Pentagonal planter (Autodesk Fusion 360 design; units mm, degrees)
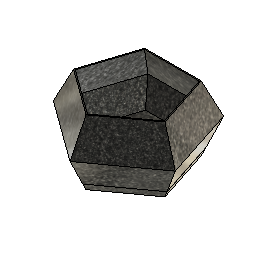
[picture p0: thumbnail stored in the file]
sketch "Sketch1" plane through (0, 0, 0) normal (0, 0, 1) x axis (1, 0, 0)
  line L1 (-70.5342, -22.918) -> (-43.5926, 60)
  line L2 (0, -74.1641) -> (-70.5342, -22.918)
  line L3 (70.5342, -22.918) -> (0, -74.1641)
  line L4 (43.5926, 60) -> (70.5342, -22.918)
  line L5 (-43.5926, 60) -> (43.5926, 60)
  point P1 (0, 0)
  point P7 (0, 0)
  coincident P1 P7
  horizontal L5
  dimension "d1" distance P7 L5 = 60
work_plane "WorkPlane1" AlongDistance 50
sketch "Sketch2" plane through (0, 0, 50) normal (0, 0, 1) x axis (1, 0, 0)
  line L1 (-94.0456, -30.5573) -> (-58.1234, 80)
  line L2 (0, -98.8854) -> (-94.0456, -30.5573)
  line L3 (94.0456, -30.5573) -> (0, -98.8854)
  line L4 (58.1234, 80) -> (94.0456, -30.5573)
  line L5 (-58.1234, 80) -> (58.1234, 80)
  point P1 (0, 0)
  point P7 (0, 0)
  coincident P1 P7
  horizontal L5
  dimension "d3" distance P7 L5 = 80
loft "Loft1" sketch "Sketch1" + "Sketch2" bodies "inferior"
mirror "Mirror1" mirrorStitchTolerance 0.1
shell "Shell1" innerThickness 1.6
work_plane "WorkPlane2" AlongDistance 10
split "Split1" bodies "superior"
sketch "Sketch3" plane through (0, 0, 1.6) normal (0, 0, 1) x axis (-1, 0, 0)
  line L1 (42.8055, -58.9167) -> (-42.8055, -58.9167)
  line L2 (69.2608, 22.5042) -> (42.8055, -58.9167)
  line L3 (0, 72.8251) -> (69.2608, 22.5042)
  line L4 (-69.2608, 22.5042) -> (0, 72.8251)
  line L5 (-42.8055, -58.9167) -> (-69.2608, 22.5042)
  line L6 (0, 62.9366) -> (59.8562, 19.4485)
  line L7 (-59.8562, 19.4485) -> (0, 62.9366)
  line L8 (-36.9932, -50.9167) -> (-59.8562, 19.4485)
  line L9 (36.9932, -50.9167) -> (-36.9932, -50.9167)
  line L10 (59.8562, 19.4485) -> (36.9932, -50.9167)
  line L11 (0, 57.9923) -> (55.1539, 17.9206)
  line L12 (-55.1539, 17.9206) -> (0, 57.9923)
  line L13 (-34.087, -46.9167) -> (-55.1539, 17.9206)
  line L14 (34.087, -46.9167) -> (-34.087, -46.9167)
  line L15 (55.1539, 17.9206) -> (34.087, -46.9167)
  line L16 (15, -46.9167) -> (15, -50.9167)
  line L17 (-15, -46.9167) -> (-15, -50.9167)
  line L18 (0, -22.5) -> (0, -1.75)
  line L19 (49.2557, -0.2322) -> (53.06, -1.4683)
  line L20 (39.9852, -28.7639) -> (43.7894, -30)
  line L21 (15.4417, 46.7732) -> (17.7929, 50.0093)
  line L22 (39.7122, 29.1397) -> (42.0634, 32.3757)
  line L23 (-39.7122, 29.1397) -> (-42.0634, 32.3757)
  line L24 (-15.4417, 46.7732) -> (-17.7929, 50.0093)
  line L25 (-39.9852, -28.7639) -> (-43.7894, -30)
  line L26 (-49.2557, -0.2322) -> (-53.06, -1.4683)
  point P17 (15, -50.9167)
  point P18 (15, -46.9167)
  point P19 (-15, -50.9167)
  point P20 (-15, -46.9167)
  coincident L9 P17
  coincident L14 P18
  perpendicular L14 L16
  coincident L9 P19
  coincident L14 P20
  perpendicular L14 L17
  symmetric L16 L17 L18
  dimension "d10" = -8
  dimension "d11" = -12
  dimension "d12" distance L16 L17 = 30
  dimension "d14" C-Pattern1-Angle = 360
extrude "Extrude2" add sketch "Sketch3" profile of L6 L10 L7 L8 L9 L11 L15 L12 L13 L14 L16 L17 L19 L20 L21 L22 L23 L24 L25 L26 to an object offset 2
work_plane "WorkPlane3" AlongDistance 4
boundary_fill "BoundaryFill9"
sketch "Sketch4" plane through (0, 0, 12) normal (0, 0, 1) x axis (-1, 0, 0)
  line L1 (15, -50.9167) -> (-15, -50.9167)
  line L2 (15, -46.9167) -> (15, -50.9167)
  line L3 (-15, -46.9167) -> (15, -46.9167)
  line L4 (-15, -50.9167) -> (-15, -46.9167)
  line L5 (-15.5, -46.4167) -> (15.5, -46.4167)
  line L6 (-15.5, -51.4167) -> (-15.5, -46.4167)
  line L7 (15.5, -51.4167) -> (-15.5, -51.4167)
  line L8 (15.5, -46.4167) -> (15.5, -51.4167)
  line L9 (53.69, -1.1473) -> (44.1105, -30.63)
  line L10 (44.1105, -30.63) -> (39.3552, -29.0849)
  line L11 (39.3552, -29.0849) -> (48.9347, 0.3978)
  line L12 (48.9347, 0.3978) -> (53.69, -1.1473)
  line L13 (17.6822, 50.7077) -> (42.7618, 32.4864)
  line L14 (42.7618, 32.4864) -> (39.8228, 28.4413)
  line L15 (39.8228, 28.4413) -> (14.7433, 46.6626)
  line L16 (14.7433, 46.6626) -> (17.6822, 50.7077)
  line L17 (-42.7618, 32.4864) -> (-17.6822, 50.7077)
  line L18 (-17.6822, 50.7077) -> (-14.7433, 46.6626)
  line L19 (-14.7433, 46.6626) -> (-39.8228, 28.4413)
  line L20 (-39.8228, 28.4413) -> (-42.7618, 32.4864)
  line L21 (-44.1105, -30.63) -> (-53.69, -1.1473)
  line L22 (-53.69, -1.1473) -> (-48.9347, 0.3978)
  line L23 (-48.9347, 0.3978) -> (-39.3552, -29.0849)
  line L24 (-39.3552, -29.0849) -> (-44.1105, -30.63)
  circle C1 centre (0, -30) radius 4
  circle C2 centre (28.5317, -9.2705) radius 4
  circle C3 centre (17.6336, 24.2705) radius 4
  circle C4 centre (-17.6336, 24.2705) radius 4
  circle C5 centre (-28.5317, -9.2705) radius 4
  circle C6 centre (0, 0) radius 4
  point P1 (0, 0)
  point P31 (0, 0)
  point P26 (0, -30)
  coincident P1 P31
  dimension "d18" = 0.5
  dimension "d21" diameter C1 = 8
  dimension "d22" distance P1 P26 = 30
  dimension "d25" diameter C6 = 8
  dimension "d20" C-Pattern1-Angle = 360
  dimension "d24" C-Pattern2-Angle = 360
extrude "Extrude3" cut sketch "Sketch4" + "Sketch3" profile of S1:L1 S1:L2 S1:L3 S1:L4 S1:L5 S1:L6 S1:L8 S1:L7 S1:L9 S1:L10 S1:L11 S1:L12 S1:L13 S1:L14 S1:L15 S1:L16 S1:L17 S1:L18 S1:L19 S1:L20 S1:L21 S1:L22 S1:L23 S1:L24 blind -10
extrude "Extrude4" cut sketch "Sketch4" profile of C1 C2 C3 C4 C5 C6 no distance stored
named bodies: "inferior", "superior"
